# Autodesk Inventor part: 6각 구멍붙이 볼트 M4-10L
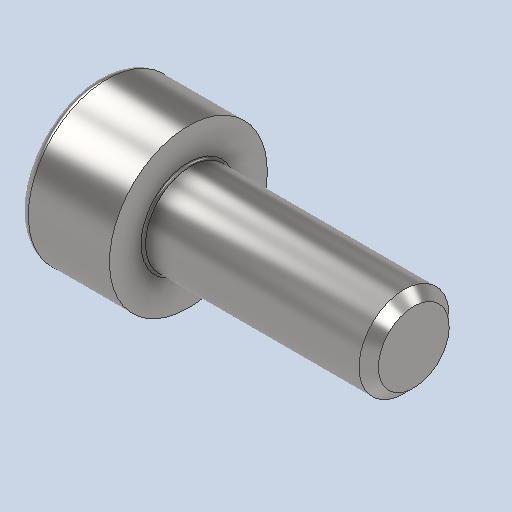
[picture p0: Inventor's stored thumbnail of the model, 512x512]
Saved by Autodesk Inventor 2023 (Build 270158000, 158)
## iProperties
Created: 2025-04
Part Number: 6각 구멍붙이 볼트 M4-10L
Material: 강철, 연강
Description: 6각머리 태핑 나사
Document SubType Name: Modeling
Designer: user
Density: 7.86 g/cm^3
Appearance: 기본값
Author: jhkim
Revision Number: 1
Sending System: Autodesk Inventor 2026
Preprocessor: ST-DEVELOPER v20.1
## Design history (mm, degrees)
feature "Solid1"
node "솔리드1"
